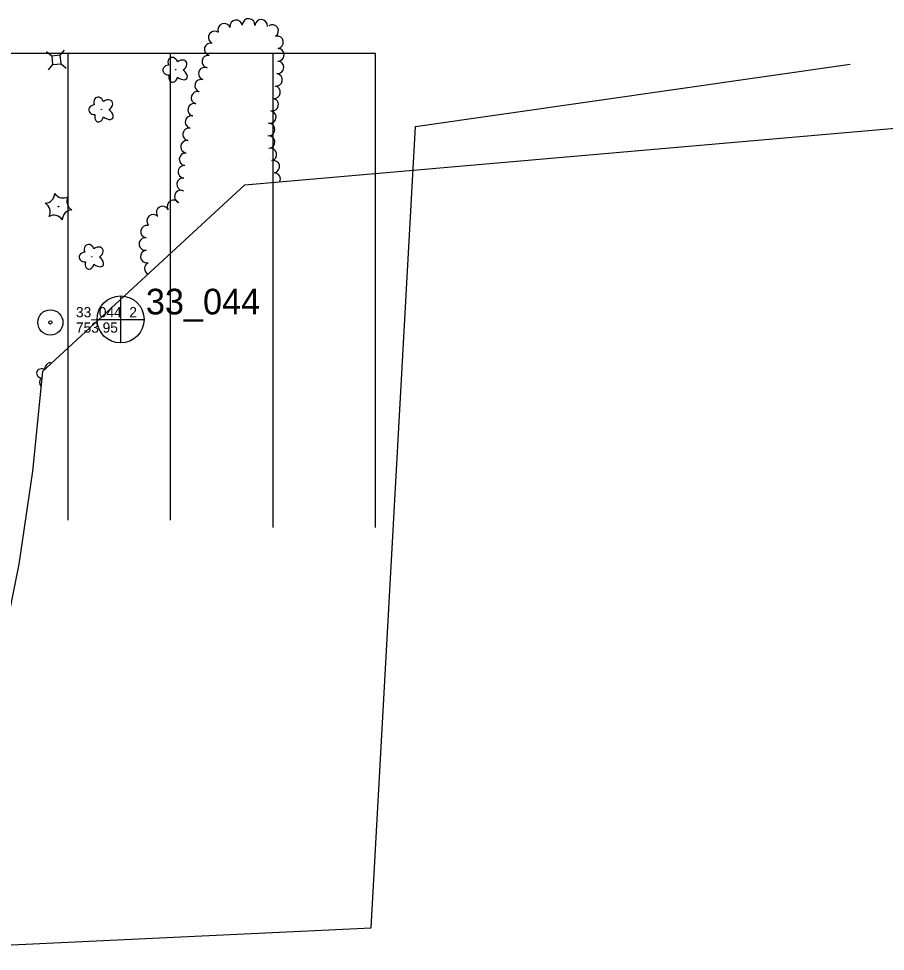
# Model space of a CAD drawing. Extents: x 589250 to 1188077, y 162953 to 363065.
# Drawn here: x 595257 to 595764, y 174363 to 174909 of the extents above; entities that cross this region are included whole.
import ezdxf

# ---------------------------------------------------------------- set-up
doc = ezdxf.new("R2010")
doc.units = 0
for name, color, linetype in [('E_DRN_DrainTile', 7, 'Continuous'), ('E_LAND_TreeLine_P', 7, 'Continuous'), ('E_LAND_Vegetation', 7, 'Continuous'), ('E_MAP_Limits', 7, 'Continuous'), ('E_MAP_PassPoints', 7, 'Continuous'), ('E_MAP_PhotoCenter', 7, 'Continuous'), ('E_UTL_AG_Bold', 7, 'Continuous')]:
    doc.layers.add(name, color=color, linetype=linetype)

msp = doc.modelspace()

# ---------------------------------------------------------------- linework, layer by layer
at = {"layer": 'E_DRN_DrainTile'}
for p, q in [((595285.8, 174615.65), (595285.8, 174888.93)), ((595345.8, 174615.65), (595345.8, 174888.93)), ((595405.8, 174611.39), (595405.8, 174888.93)), ((595465.8, 174611.39), (595465.8, 174888.93)), ((595489.3, 174846.28), (595743.78, 174882.86)), ((595463.39, 174376.95), (595489.3, 174846.28)), ((595172.34, 174363.23), (595463.39, 174376.95))]:
    msp.add_line(p, q, dxfattribs=at)
msp.add_lwpolyline([(595465.8, 174888.93), (595345.8, 174888.93), (595225.8, 174888.93)], dxfattribs=at)
at = {"layer": 'E_LAND_TreeLine_P'}
for centre, start, end in [((595391.5, 174905.75), 355.6373, 175.6373), ((595377.16, 174902.87), 19.2507, 199.2507), ((595384.19, 174904.96), 6.7037, 186.7037), ((595398.84, 174905.19), 355.6373, 175.6373), ((595405.32, 174902.2), 302.9985, 122.9985), ((595371.65, 174898.41), 51.405, 231.405), ((595408.22, 174895.59), 279.7393, 99.7393), ((595369.33, 174891.52), 75.3509, 255.3509), ((595367.87, 174884.31), 80.28, 260.28), ((595408.65, 174888.26), 271.7093, 91.7093), ((595408.46, 174880.9), 268.0424, 88.0424), ((595365.87, 174877.23), 72.4139, 252.4139), ((595407.56, 174873.6), 261.3226, 81.3226), ((595363.69, 174870.2), 73.4676, 253.4676), ((595361.59, 174863.14), 73.4676, 253.4676), ((595406.45, 174866.32), 261.3226, 81.3226), ((595405.3, 174859.05), 259.1907, 79.1907), ((595359.64, 174856.05), 78.0505, 258.0505), ((595403.92, 174851.82), 259.1907, 79.1907), ((595358.12, 174848.85), 78.0505, 258.0505), ((595356.69, 174841.63), 80.3009, 260.3009), ((595403.16, 174844.52), 267.871, 87.871), ((595403.17, 174837.17), 275.3918, 95.3918), ((595355.45, 174834.37), 80.3009, 260.3009), ((595404.26, 174829.9), 283.3556, 103.3556), ((595354.59, 174827.06), 84.7221, 264.7221), ((595353.91, 174819.73), 84.7221, 264.7221), ((595405.96, 174822.74), 283.3556, 103.3556), ((595406.43, 174815.45), 335.0774, 88.8608), ((595353.13, 174812.41), 83.3354, 263.3354), ((595351.83, 174805.24), 62.0134, 242.0134), ((595347.49, 174799.57), 31.5228, 211.5228), ((595335.61, 174791.02), 42.8383, 222.8383), ((595341.12, 174795.87), 29.8358, 209.8358), ((595332.02, 174784.68), 80.6268, 260.6268), ((595331, 174777.42), 96.4622, 276.4622), ((595331.83, 174770.1), 96.4622, 276.4622), ((595334.29, 174763.18), 116.5953, 243.446)]:
    msp.add_arc(centre, 3.68, start, end, dxfattribs=at)
at = {"layer": 'E_LAND_Vegetation'}
for centre, radius in [((595348.72, 174879.6), 0.128), ((595305.29, 174856.35), 0.128), ((595280.17, 174799.37), 0.167), ((595299.69, 174770.08), 0.128)]:
    msp.add_circle(centre, radius, dxfattribs=at)
for centre, radius, start, end in [((595272.06, 174807.21), 5.9, 273.0879, 358.8528), ((595282.9, 174810.31), 5.9, 213.0879, 298.8528), ((595269.39, 174796.27), 5.9, 333.0832, 58.8481), ((595291.02, 174802.48), 5.91, 153.1276, 238.8037), ((595288.27, 174791.54), 5.9, 93.0879, 178.8528), ((595277.43, 174788.43), 5.9, 33.0879, 118.8528)]:
    msp.add_arc(centre, radius, start, end, dxfattribs=at)
for centre, major_axis, ratio, start_param, end_param in [((595344.75, 174879.35), (3.45, 0.23), 0.832022, 1.570796, 4.712389), ((595347.21, 174883.2), (1.26, -3.39), 0.782863, 1.570796, 4.712389), ((595351.5, 174881.78), (-3.49, -2.38), 0.691916, 1.570796, 4.712389), ((595347.44, 174875.8), (0.95, 3.5), 0.716896, 1.570796, 4.712389), ((595351.55, 174877.25), (-3.78, 2.88), 0.560249, 1.570796, 4.712389), ((595303.78, 174859.95), (1.26, -3.39), 0.782863, 1.570796, 4.712389), ((595308.08, 174858.52), (-3.49, -2.38), 0.691916, 1.570796, 4.712389), ((595301.32, 174856.09), (3.45, 0.23), 0.832022, 1.570796, 4.712389), ((595308.13, 174854), (-3.78, 2.88), 0.560249, 1.570796, 4.712389), ((595304.02, 174852.55), (0.95, 3.5), 0.716896, 1.570796, 4.712389), ((595295.71, 174769.82), (3.45, 0.23), 0.832022, 1.570796, 4.712389), ((595298.18, 174773.68), (1.26, -3.39), 0.782863, 1.570796, 4.712389), ((595302.47, 174772.26), (-3.49, -2.38), 0.691916, 1.570796, 4.712389), ((595302.52, 174767.73), (-3.78, 2.88), 0.560249, 1.570796, 4.712389), ((595298.41, 174766.28), (0.95, 3.5), 0.716896, 1.570796, 4.712389), ((595274.81, 174703.67), (-0.59, -4.18), 0.691916, 2.933744, 4.712389), ((595270.87, 174701.45), (3.35, -1.35), 0.782863, 1.570796, 4.712389), ((595272.06, 174697.04), (2.15, 2.7), 0.832022, 1.570796, 3.141034)]:
    msp.add_ellipse(centre, major_axis=major_axis, ratio=ratio, start_param=start_param, end_param=end_param, dxfattribs=at)
at = {"layer": 'E_MAP_Limits'}
for p, q in [((595389.31, 174812.12), (595979.4, 174863.4)), ((595270.78, 174702.87), (595389.31, 174812.12)), ((595270.78, 174702.87), (595264.85, 174644.45)), ((595264.85, 174644.45), (595256.95, 174589.94)), ((595256.95, 174589.94), (595248.98, 174550.03))]:
    msp.add_line(p, q, dxfattribs=at)
at = {"layer": 'E_MAP_PassPoints'}
for radius in [7.38, 7.38, 0.945, 0.945]:
    msp.add_circle((595275.4, 174731.53), radius, dxfattribs=at)
at = {"layer": 'E_MAP_PhotoCenter'}
for p, q in [((595316.45, 174747.06), (595316.38, 174719.66)), ((595316.45, 174747.06), (595316.38, 174719.66)), ((595302.76, 174733.26), (595330.22, 174733.24)), ((595302.76, 174733.26), (595330.22, 174733.24))]:
    msp.add_line(p, q, dxfattribs=at)
msp.add_circle((595316.5, 174733.27), 13.78, dxfattribs=at)
msp.add_circle((595316.5, 174733.27), 13.78, dxfattribs=at)
at = {"layer": 'E_UTL_AG_Bold'}
for p, q in [((595276.22, 174887.52), (595273.14, 174890.08)), ((595281.2, 174887.98), (595276.22, 174887.52)), ((595276.22, 174887.52), (595276.67, 174882.54)), ((595281.2, 174887.98), (595283.76, 174891.05)), ((595281.65, 174883), (595281.2, 174887.98)), ((595276.67, 174882.54), (595274.11, 174879.47)), ((595276.67, 174882.54), (595281.65, 174883)), ((595281.65, 174883), (595284.72, 174880.44))]:
    msp.add_line(p, q, dxfattribs=at)

# ---------------------------------------------------------------- texts
at = {"layer": 'E_MAP_PassPoints'}
for s, p in [('33_044_2', (595290.4, 174734.52)), ('33_044_2', (595290.4, 174734.52)), ('753.95', (595290.4, 174725.52)), ('753.95', (595290.4, 174725.52))]:
    msp.add_text(s, height=6, dxfattribs=at).set_placement(p)
at = {"layer": 'E_MAP_PhotoCenter'}
msp.add_text('33_044', height=15, dxfattribs=at).set_placement((595331.35, 174736.24))
msp.add_text('33_044', height=15, dxfattribs=at).set_placement((595331.35, 174736.24))

doc.saveas('drawing.dxf')
